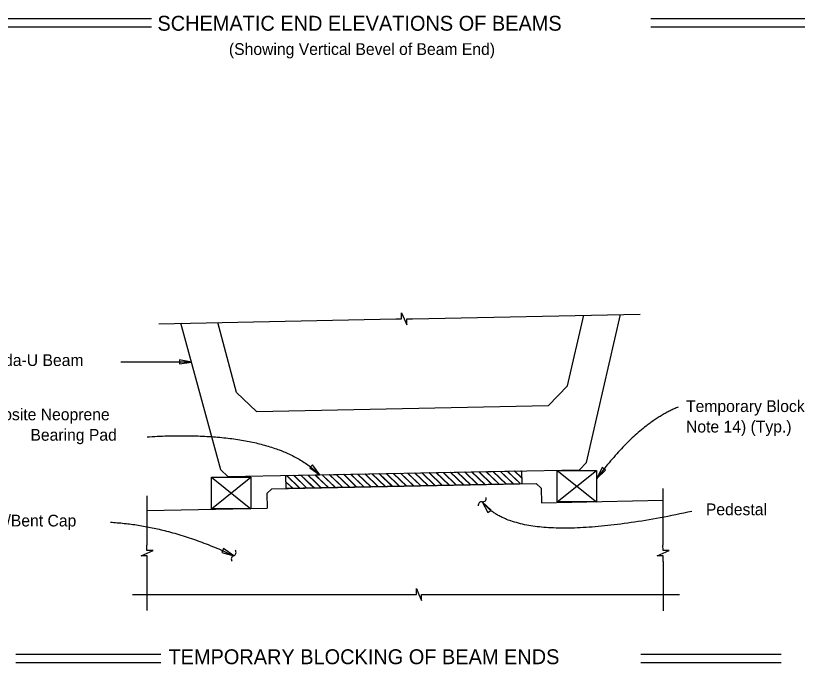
# Model space of a CAD drawing. Extents: x 0.5 to 29.5, y 0.9 to 17.7.
# Drawn here: x 10.3 to 20.37, y 0.9 to 9.26 of the extents above; entities that cross this region are included whole.
import ezdxf

# ---------------------------------------------------------------- set-up
doc = ezdxf.new("R2010")
doc.units = 0
for name, color, linetype in [('BeamConc', 7, 'Continuous'), ('BeamConc_h', 7, 'Continuous'), ('Dimension', 7, 'Continuous'), ('Miscellaneous', 7, 'Continuous'), ('TextStructures', 7, 'Continuous'), ('Wood', 7, 'Continuous')]:
    doc.layers.add(name, color=color, linetype=linetype)

msp = doc.modelspace()

# ---------------------------------------------------------------- linework, layer by layer
at = {"layer": 'BeamConc'}
for p, q in [((17.648, 3.497), (18.085, 5.406)), ((12.938, 3.402), (12.425, 5.293)), ((17.561, 3.406), (17.648, 3.497)), ((13.028, 3.316), (12.938, 3.402)), ((13.028, 3.316), (17.561, 3.406)), ((13.594, 3.16), (17.002, 3.229)), ((17.002, 3.229), (17.066, 3.167)), ((13.533, 3.097), (13.594, 3.16)), ((17.066, 3.167), (17.07, 2.98)), ((13.533, 3.097), (13.536, 2.909)), ((17.07, 2.98), (18.633, 3.011)), ((11.986, 2.878), (13.536, 2.909))]:
    msp.add_line(p, q, dxfattribs=at)
at = {"layer": 'BeamConc_h'}
for p, q in [((17.404, 4.487), (17.613, 5.396)), ((13.142, 4.402), (12.898, 5.302)), ((17.404, 4.487), (17.16, 4.232)), ((13.142, 4.402), (13.397, 4.157)), ((13.397, 4.157), (17.16, 4.232))]:
    msp.add_line(p, q, dxfattribs=at)
at = {"layer": 'Dimension'}
for p, q in [((12.044, 9.216), (4.794, 9.216)), ((12.044, 9.216), (4.794, 9.216)), ((26.575, 9.216), (18.476, 9.216)), ((26.575, 9.216), (18.476, 9.216)), ((12.044, 9.108), (4.794, 9.108)), ((12.044, 9.108), (4.794, 9.108)), ((26.575, 9.108), (18.476, 9.108)), ((26.575, 9.108), (18.476, 9.108)), ((12.141, 5.287), (15.194, 5.348)), ((15.407, 5.352), (18.34, 5.411)), ((18.634, 3.165), (18.634, 2.435)), ((11.986, 3.068), (11.986, 2.435)), ((11.986, 2.223), (11.986, 1.593)), ((18.638, 2.223), (18.638, 1.585)), ((11.8, 1.797), (15.385, 1.797)), ((15.597, 1.797), (18.847, 1.797)), ((12.167, 1.024), (10.299, 1.024)), ((20.157, 1.024), (18.35, 1.024)), ((12.167, 0.916), (10.299, 0.916)), ((20.157, 0.916), (18.35, 0.916))]:
    msp.add_line(p, q, dxfattribs=at)
for points in [[(15.194, 5.348), (15.267, 5.349), (15.265, 5.427), (15.3, 5.35), (15.336, 5.273), (15.334, 5.351), (15.407, 5.352)], [(11.99, 2.223), (11.989, 2.295), (11.911, 2.294), (11.988, 2.329), (12.065, 2.364), (11.987, 2.363), (11.986, 2.435)], [(18.638, 2.223), (18.637, 2.295), (18.56, 2.294), (18.636, 2.329), (18.713, 2.364), (18.636, 2.363), (18.634, 2.435)], [(15.385, 1.798), (15.457, 1.798), (15.457, 1.875), (15.491, 1.798), (15.525, 1.72), (15.525, 1.798), (15.597, 1.798)]]:
    msp.add_lwpolyline(points, dxfattribs=at)
for points in [[(12.561, 4.793), (12.405, 4.822), (12.404, 4.769)], [(14.213, 3.339), (14.121, 3.468), (14.083, 3.431)], [(17.781, 3.292), (17.895, 3.401), (17.853, 3.433)], [(16.307, 2.993), (16.378, 2.852), (16.421, 2.883)], [(13.104, 2.297), (12.974, 2.388), (12.952, 2.34)]]:
    msp.add_lwpolyline(points, close=True, dxfattribs=at)
for centre, start, end in [((16.314, 3.037), 260.5328, 12.26), ((16.299, 2.949), 80.5328, 192.26), ((13.09, 2.339), 288.7395, 40.4667), ((13.118, 2.255), 108.7395, 220.4667)]:
    msp.add_arc(centre, 0.0447, start, end, dxfattribs=at)
for points in [[(11.651, 4.795), (12.155, 4.801), (12.561, 4.793)], [(18.828, 4.212), (18.303, 3.997), (17.781, 3.292)], [(11.988, 3.829), (13.617, 3.931), (14.213, 3.339)], [(19.006, 2.867), (16.757, 2.381), (16.307, 2.993)], [(11.516, 2.729), (12.288, 2.685), (13.104, 2.297)]]:
    msp.add_open_spline(points, degree=2, dxfattribs=at)
at = {"layer": 'Miscellaneous'}
for p, q in [((13.953, 3.168), (13.783, 3.331)), ((13.956, 3.168), (13.787, 3.331)), ((14.045, 3.169), (13.875, 3.333)), ((14.048, 3.169), (13.878, 3.333)), ((14.108, 3.199), (13.967, 3.335)), ((14.109, 3.201), (13.97, 3.335)), ((14.153, 3.246), (14.058, 3.336)), ((14.154, 3.248), (14.062, 3.336)), ((14.197, 3.293), (14.15, 3.338)), ((14.199, 3.295), (14.154, 3.338)), ((14.242, 3.34), (14.242, 3.34)), ((14.412, 3.177), (14.244, 3.338)), ((14.415, 3.177), (14.246, 3.34)), ((14.504, 3.179), (14.334, 3.342)), ((14.507, 3.179), (14.337, 3.342)), ((14.595, 3.18), (14.425, 3.344)), ((14.599, 3.181), (14.429, 3.344)), ((14.687, 3.182), (14.517, 3.346)), ((14.691, 3.182), (14.521, 3.346)), ((14.779, 3.184), (14.609, 3.347)), ((14.782, 3.184), (14.612, 3.347)), ((14.871, 3.186), (14.701, 3.349)), ((14.874, 3.186), (14.704, 3.349)), ((14.962, 3.188), (14.792, 3.351)), ((14.966, 3.188), (14.796, 3.351)), ((15.054, 3.19), (14.884, 3.353)), ((15.058, 3.19), (14.888, 3.353)), ((15.146, 3.191), (14.976, 3.355)), ((15.149, 3.192), (14.979, 3.355)), ((15.238, 3.193), (15.068, 3.357)), ((15.241, 3.193), (15.071, 3.357)), ((15.329, 3.195), (15.16, 3.358)), ((15.333, 3.195), (15.163, 3.358)), ((15.421, 3.197), (15.251, 3.36)), ((15.425, 3.197), (15.255, 3.36)), ((15.513, 3.199), (15.343, 3.362)), ((15.516, 3.199), (15.346, 3.362)), ((15.605, 3.201), (15.435, 3.364)), ((15.608, 3.201), (15.438, 3.364)), ((15.697, 3.202), (15.527, 3.366)), ((15.7, 3.203), (15.53, 3.366)), ((15.788, 3.204), (15.618, 3.368)), ((15.792, 3.204), (15.622, 3.368)), ((15.88, 3.206), (15.71, 3.369)), ((15.883, 3.206), (15.713, 3.369)), ((15.972, 3.208), (15.802, 3.371)), ((15.975, 3.208), (15.805, 3.371)), ((16.064, 3.21), (15.894, 3.373)), ((16.067, 3.21), (15.897, 3.373)), ((16.155, 3.212), (15.985, 3.375)), ((16.159, 3.212), (15.989, 3.375)), ((16.247, 3.213), (16.077, 3.377)), ((16.25, 3.214), (16.08, 3.377)), ((16.339, 3.215), (16.169, 3.379)), ((16.342, 3.215), (16.172, 3.379)), ((16.431, 3.217), (16.261, 3.38)), ((16.434, 3.217), (16.264, 3.381)), ((16.522, 3.219), (16.352, 3.382)), ((16.526, 3.219), (16.356, 3.382)), ((16.614, 3.221), (16.444, 3.384)), ((16.617, 3.221), (16.448, 3.384)), ((16.706, 3.223), (16.536, 3.386)), ((16.709, 3.223), (16.539, 3.386)), ((16.798, 3.224), (16.628, 3.388)), ((16.801, 3.225), (16.631, 3.388)), ((16.813, 3.299), (16.719, 3.39)), ((16.813, 3.303), (16.723, 3.39)), ((16.812, 3.378), (16.798, 3.391)), ((16.812, 3.381), (16.802, 3.391)), ((16.812, 3.391), (16.811, 3.391)), ((13.865, 3.166), (13.78, 3.247)), ((13.861, 3.166), (13.78, 3.244)), ((14.228, 3.173), (14.154, 3.244)), ((14.232, 3.173), (14.156, 3.246)), ((14.32, 3.175), (14.199, 3.291)), ((14.324, 3.175), (14.201, 3.293)), ((14.137, 3.171), (14.109, 3.198)), ((14.14, 3.171), (14.111, 3.199))]:
    msp.add_line(p, q, dxfattribs=at)
msp.add_lwpolyline([(13.778, 3.331), (16.812, 3.391), (16.815, 3.225), (13.781, 3.164)], close=True, dxfattribs=at)
at = {"layer": 'Wood'}
for p, q in [((17.272, 3.397), (17.78, 2.991)), ((17.272, 2.991), (17.78, 3.397)), ((12.818, 3.308), (13.326, 2.902)), ((12.818, 2.902), (13.326, 3.308))]:
    msp.add_line(p, q, dxfattribs=at)
for points in [[(17.272, 3.397), (17.78, 3.397), (17.78, 2.991), (17.272, 2.991)], [(12.818, 3.308), (13.326, 3.308), (13.326, 2.902), (12.818, 2.902)]]:
    msp.add_lwpolyline(points, close=True, dxfattribs=at)

# ---------------------------------------------------------------- texts
at = {"layer": 'Dimension'}
for s, p in [('Temporary Blocking (See ', (18.931, 4.149)), ('Composite Neoprene', (9.596, 4.043)), ('Note 14) (Typ.)', (18.931, 3.885)), ('Bearing Pad', (10.486, 3.779))]:
    msp.add_text(s, height=0.1512, dxfattribs=at).set_placement(p)
at = {"layer": 'TextStructures'}
for s, height, p in [('SCHEMATIC END ELEVATIONS OF BEAMS', 0.192, (12.122, 9.063)), ('(Showing Vertical Bevel of Beam End)', 0.1512, (13.043, 8.751)), ('Florida-U Beam', 0.1512, (9.754, 4.742)), ('Pedestal', 0.1512, (19.187, 2.819)), ('Pier/Bent Cap', 0.1512, (9.818, 2.674)), ('TEMPORARY BLOCKING OF BEAM ENDS', 0.192, (12.264, 0.899))]:
    msp.add_text(s, height=height, dxfattribs=at).set_placement(p)

doc.saveas('drawing.dxf')
